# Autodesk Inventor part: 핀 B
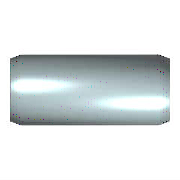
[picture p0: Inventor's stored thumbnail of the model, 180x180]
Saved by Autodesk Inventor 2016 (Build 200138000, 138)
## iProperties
Created: 2012-02
Part Number: 핀 B
Material: 강철, 연강
Description: 평행 핀
Document SubType Name: Modeling
Standard: KS B 1320
Designer: mduedu
Standards Organization: KS
Language: ko-KR
Size Designation: B 4 x  10
Categories: <MemberInstance><Categories><Category DisplayName="조임쇠" InternalName="e4da775c-781d-43d5-af7c-5136215cf5a6" Mnemonic="FSTN"><Category DisplayName="핀" InternalNa
Density: 1 g/cm^3
Appearance: 노란색
IsCustomPart: 1
Author: mduedu
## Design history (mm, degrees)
sketch "스케치"
  geometry: C1 r 2 at (0, 0); 1 further point
  constraints: 1 centre point, 1 coincident
  dimensions: "d1" = 4 diameter of C1 (= NND)
extrude "본체" new body sketch "스케치" distance "d2" = 10 (= NLG); taper "d3" = 0 deg
chamfer "스케치2" distance "d8" = 0.63 (= PHH); stored, may be unused: angle "d9" = 15 deg (= FAWI), second distance "d12" = 0.63 (= PHH)
body "Solid1"
chamfer "모따기1" distance "d4" = 0.63 (= PHH); stored, may be unused: angle "d5" = 15 deg (= FAWI), second distance "d11" = 0.63 (= PHH)
other parameters: "NND" = 4 [user parameter; used in 1 equation term], "NLG" = 10 [user parameter; used in 1 equation term], "PHH" = 0.63 [user parameter; used in 4 equation terms], "FAWI" = 15 deg [user parameter; used in 2 equation terms], "d13" = 0, "d15" = 0, "d16" = 0, "KAH" = 0.5 [user parameter]
